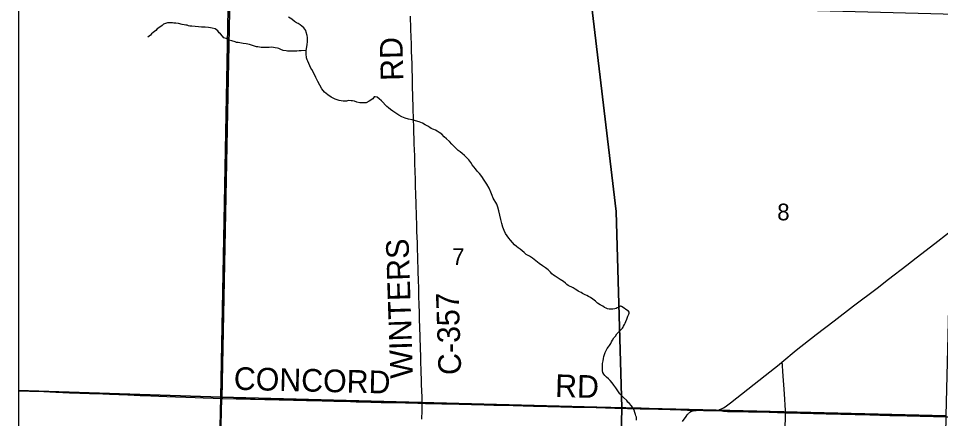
# Model space of a CAD drawing. Extents: x 0 to 34, y 0 to 22.
# Drawn here: x 23.9 to 25.055, y 17.356 to 17.857 of the extents above; entities that cross this region are included whole.
import ezdxf

# ---------------------------------------------------------------- set-up
doc = ezdxf.new("R2010")
doc.units = 0
for name, color, linetype in [('GM_X_County_Road', 7, 'Continuous'), ('GM_X_County_Road_Text', 7, 'Continuous'), ('GM_X_Minor_River', 7, 'Continuous'), ('GM_X_Section', 7, 'Continuous'), ('GM_X_Section_Text', 7, 'Continuous'), ('GM_X_State_Route', 7, 'Continuous'), ('GM_X_Township', 7, 'Continuous'), ('GM_X_Township_Road', 7, 'Continuous'), ('GM_X_Unincorporated', 7, 'Continuous'), ('SC_Scratch1', 7, 'Continuous'), ('SH_Border', 7, 'Continuous'), ('SH_Cut_Line', 7, 'Continuous')]:
    doc.layers.add(name, color=color, linetype=linetype)

msp = doc.modelspace()

# ---------------------------------------------------------------- linework, layer by layer
at = {"layer": 'GM_X_County_Road'}
for points in [[(24.4058, 17.3747), (24.4057, 17.3759), (24.4057, 17.3785), (24.4056, 17.3832), (24.4054, 17.3894), (24.4051, 17.399), (24.4048, 17.4059), (24.4046, 17.4119), (24.4044, 17.419), (24.4042, 17.4231), (24.4039, 17.4327), (24.4035, 17.4443), (24.4029, 17.4706), (24.4026, 17.4792), (24.4024, 17.4869), (24.402, 17.4996), (24.4017, 17.5074), (24.4014, 17.5178), (24.401, 17.5301), (24.4008, 17.5381), (24.4006, 17.5438), (24.4003, 17.5533), (24.4002, 17.559), (24.4, 17.5673), (24.3997, 17.5766), (24.3995, 17.5819), (24.3992, 17.5908), (24.3989, 17.5993), (24.3987, 17.6082), (24.3985, 17.6139), (24.3983, 17.6205), (24.3982, 17.6257), (24.3979, 17.6354), (24.3975, 17.648), (24.3973, 17.6546), (24.397, 17.6655), (24.3967, 17.6745), (24.3964, 17.6845), (24.3961, 17.6921), (24.3959, 17.6996), (24.3956, 17.7067), (24.3954, 17.713), (24.3951, 17.7226), (24.3949, 17.7285), (24.3948, 17.7337), (24.3946, 17.7412), (24.3944, 17.7484), (24.3942, 17.7555), (24.3937, 17.7754), (24.3935, 17.7832), (24.3933, 17.7927), (24.3931, 17.7995), (24.3928, 17.8082), (24.3925, 17.8153), (24.3924, 17.8213), (24.3923, 17.8245), (24.3922, 17.828), (24.3921, 17.8304), (24.392, 17.8331), (24.3916, 17.8439), (24.391, 17.8596)], [(23.9, 17.3905), (23.9139, 17.39), (23.9202, 17.3897), (23.9316, 17.3893), (23.9469, 17.3887), (23.9641, 17.388), (23.9767, 17.3875), (23.9888, 17.387), (24.0057, 17.3864), (24.014, 17.3861), (24.0369, 17.3852), (24.0524, 17.3846), (24.0658, 17.3841), (24.0859, 17.3833), (24.0968, 17.3829), (24.1097, 17.3824), (24.1215, 17.382), (24.1314, 17.3816), (24.1439, 17.3812), (24.155, 17.3809)], [(24.155, 17.3809), (24.156, 17.3809), (24.1733, 17.3805), (24.1853, 17.3802), (24.1965, 17.3799), (24.2104, 17.3796), (24.2241, 17.3793), (24.2409, 17.3789), (24.2607, 17.3784), (24.2769, 17.378), (24.2952, 17.3775), (24.3194, 17.3768), (24.3229, 17.3767), (24.3415, 17.3761), (24.3545, 17.3758), (24.3696, 17.3755), (24.3849, 17.3751), (24.4001, 17.3748), (24.4058, 17.3747), (24.4101, 17.3746), (24.4188, 17.3744), (24.4302, 17.3742), (24.452, 17.3737), (24.4677, 17.3733), (24.4709, 17.3732), (24.4834, 17.3728), (24.4956, 17.3725), (24.5067, 17.3722), (24.5451, 17.3712), (24.5632, 17.3708), (24.5795, 17.3704), (24.5946, 17.37), (24.6095, 17.3697), (24.6238, 17.3693), (24.6472, 17.3688), (24.6631, 17.3683), (24.679, 17.3679), (24.7017, 17.3673), (24.7163, 17.3669), (24.7296, 17.3666), (24.7315, 17.3665), (24.7363, 17.3664), (24.7382, 17.3663), (24.7395, 17.3661), (24.741, 17.3657), (24.7423, 17.3652), (24.7435, 17.3648)], [(24.7435, 17.3648), (24.7444, 17.3651), (24.7451, 17.3653), (24.7458, 17.3655), (24.7463, 17.3656), (24.7472, 17.3657), (24.7478, 17.3658), (24.7489, 17.3658), (24.7499, 17.3659), (24.752, 17.366), (24.7536, 17.3659), (24.7583, 17.3658), (24.7667, 17.3655), (24.7701, 17.3655), (24.7721, 17.3656), (24.7732, 17.3657), (24.7746, 17.3659), (24.7757, 17.3661), (24.7777, 17.3666), (24.7784, 17.3668)], [(24.7784, 17.3668), (24.78, 17.3659), (24.7807, 17.3656), (24.7811, 17.3654), (24.7818, 17.3653), (24.7825, 17.3651), (24.7833, 17.365), (24.785, 17.3648), (24.7864, 17.3647), (24.7884, 17.3646), (24.8403, 17.3634), (24.8607, 17.3629), (24.8636, 17.3628), (24.9117, 17.3615), (24.9664, 17.3601), (24.9915, 17.3595), (25.0133, 17.3591), (25.0789, 17.3574)]]:
    msp.add_lwpolyline(points, dxfattribs=at)
at = {"layer": 'GM_X_Minor_River'}
for points in [[(24.2606, 17.8167), (24.2543, 17.8164), (24.2517, 17.8161), (24.2486, 17.816), (24.2465, 17.8159), (24.2442, 17.8158), (24.2423, 17.8157), (24.2372, 17.816), (24.2355, 17.8163), (24.2315, 17.8168), (24.2287, 17.8179), (24.2263, 17.8193), (24.2246, 17.8197), (24.2214, 17.8202), (24.2197, 17.8205), (24.2176, 17.8207), (24.2142, 17.8205), (24.2113, 17.8204), (24.209, 17.8203), (24.2056, 17.8204), (24.2041, 17.8206), (24.1997, 17.8211), (24.198, 17.8214), (24.1958, 17.822), (24.193, 17.8229), (24.1896, 17.8242), (24.1851, 17.8251), (24.1813, 17.8256), (24.1752, 17.8266), (24.1733, 17.8268), (24.1716, 17.8273), (24.1673, 17.8287), (24.1637, 17.8296), (24.1602, 17.8315), (24.1574, 17.8325), (24.1555, 17.8345), (24.1532, 17.8374), (24.1513, 17.8388), (24.1499, 17.8411), (24.1482, 17.8425), (24.1464, 17.8439), (24.1428, 17.8448), (24.1407, 17.8451), (24.1382, 17.8455), (24.1341, 17.8459), (24.1293, 17.846), (24.1255, 17.8464), (24.1212, 17.8469), (24.117, 17.847), (24.1149, 17.8473), (24.113, 17.8476), (24.1113, 17.8482), (24.1098, 17.8484), (24.1077, 17.8489), (24.1049, 17.8494), (24.1006, 17.8503), (24.097, 17.8508), (24.0947, 17.8511), (24.0928, 17.8513), (24.0905, 17.8514), (24.0886, 17.8515), (24.0869, 17.8513), (24.0854, 17.8508), (24.0817, 17.8496), (24.0799, 17.848), (24.0759, 17.8451), (24.0737, 17.8438), (24.0721, 17.8418), (24.0686, 17.8394), (24.0668, 17.8374), (24.0653, 17.8359), (24.0637, 17.8347), (24.0619, 17.8334)], [(24.2662, 17.7947), (24.2626, 17.8034), (24.2617, 17.8051), (24.2609, 17.8076), (24.2605, 17.8126), (24.2606, 17.8167), (24.2616, 17.8239), (24.2622, 17.8279), (24.2622, 17.83), (24.2621, 17.833), (24.2618, 17.8353), (24.2603, 17.8395), (24.2602, 17.8416), (24.2576, 17.845), (24.255, 17.8471), (24.253, 17.8489), (24.2502, 17.8503), (24.2485, 17.8514), (24.2457, 17.853), (24.2424, 17.8559), (24.2381, 17.8582)], [(24.3634, 17.7449), (24.3613, 17.7467), (24.3548, 17.7535), (24.352, 17.7562), (24.3492, 17.758), (24.3468, 17.7588), (24.3457, 17.7586), (24.3439, 17.7562), (24.3393, 17.7531), (24.3356, 17.7513), (24.332, 17.751), (24.3276, 17.7513), (24.324, 17.7521), (24.321, 17.753), (24.3186, 17.7536), (24.3169, 17.7538), (24.3136, 17.7539), (24.3108, 17.7532), (24.3066, 17.753), (24.3019, 17.754), (24.2968, 17.7557), (24.2919, 17.7583), (24.2874, 17.7612), (24.2835, 17.7645), (24.2802, 17.7686), (24.2775, 17.7732), (24.2751, 17.778), (24.2726, 17.783), (24.2702, 17.7882), (24.2675, 17.793), (24.2662, 17.7947)], [(24.6289, 17.4981), (24.6255, 17.5003), (24.6227, 17.5026), (24.6196, 17.505), (24.6166, 17.5071), (24.6139, 17.5085), (24.6119, 17.5097), (24.61, 17.5105), (24.6066, 17.5121), (24.6049, 17.5133), (24.6029, 17.5143), (24.6012, 17.5153), (24.5993, 17.5165), (24.5973, 17.5177), (24.595, 17.5193), (24.5924, 17.5206), (24.5911, 17.5209), (24.5896, 17.5219), (24.5885, 17.5223), (24.587, 17.5236), (24.5853, 17.525), (24.5827, 17.5273), (24.5788, 17.5299), (24.575, 17.5323), (24.5724, 17.534), (24.5702, 17.5354), (24.5683, 17.537), (24.5663, 17.5391), (24.5637, 17.5417), (24.5603, 17.5442), (24.5566, 17.5468), (24.5525, 17.5497), (24.5482, 17.5532), (24.5439, 17.5564), (24.54, 17.5589), (24.5362, 17.5611), (24.5334, 17.5635), (24.5286, 17.5678), (24.5262, 17.5693), (24.524, 17.5713), (24.5215, 17.5734), (24.5189, 17.5762), (24.5165, 17.5789), (24.5145, 17.5816), (24.5121, 17.5843), (24.5101, 17.5872), (24.5085, 17.591), (24.5069, 17.5953), (24.5055, 17.5998), (24.5043, 17.605), (24.5031, 17.6105), (24.5017, 17.6159), (24.5005, 17.6205), (24.4992, 17.6243), (24.4948, 17.6316), (24.4936, 17.6351), (24.4918, 17.6393), (24.4895, 17.6441), (24.4869, 17.6493), (24.4836, 17.6543), (24.4805, 17.6587), (24.4774, 17.6626), (24.4746, 17.6657), (24.4726, 17.6686), (24.4706, 17.6709), (24.4685, 17.6736), (24.4665, 17.6765), (24.4641, 17.6796), (24.4613, 17.6825), (24.4586, 17.6853), (24.456, 17.6876), (24.4532, 17.6896), (24.4507, 17.6915), (24.4483, 17.6937), (24.4457, 17.6962), (24.443, 17.6995), (24.4398, 17.7026), (24.4363, 17.7059), (24.4331, 17.7087), (24.4302, 17.7118), (24.427, 17.7141), (24.4244, 17.7155), (24.4223, 17.7167), (24.4204, 17.7175), (24.4189, 17.7183), (24.4172, 17.7191), (24.4154, 17.7201), (24.4129, 17.7217), (24.4097, 17.7237), (24.406, 17.7257), (24.4019, 17.7275), (24.3975, 17.7287), (24.3934, 17.7299), (24.3888, 17.7306), (24.3845, 17.7319), (24.3804, 17.7335), (24.3764, 17.7357), (24.3727, 17.7382), (24.3691, 17.7406), (24.366, 17.7428), (24.3634, 17.7449)], [(24.6743, 17.3535), (24.6741, 17.3573), (24.6735, 17.3588), (24.6728, 17.3606), (24.6721, 17.3632), (24.6712, 17.3663), (24.6698, 17.369), (24.668, 17.3715), (24.665, 17.375), (24.6635, 17.3763), (24.662, 17.3781), (24.658, 17.382), (24.6535, 17.3867), (24.6517, 17.389), (24.65, 17.3915), (24.6482, 17.3942), (24.646, 17.3975), (24.6438, 17.4004), (24.6414, 17.4031), (24.639, 17.4054), (24.6365, 17.4074), (24.6345, 17.4095), (24.6332, 17.4114), (24.6321, 17.4132), (24.6316, 17.4155), (24.6317, 17.4179), (24.6318, 17.4212), (24.6318, 17.4244), (24.6323, 17.4278), (24.6327, 17.4308), (24.6334, 17.4335), (24.634, 17.4359), (24.635, 17.4385), (24.6362, 17.4408), (24.6376, 17.4432), (24.639, 17.4455), (24.6402, 17.4472), (24.6413, 17.4485), (24.6419, 17.4498), (24.6431, 17.4516), (24.6443, 17.4539), (24.6459, 17.4565), (24.6479, 17.4589), (24.6496, 17.4617), (24.6518, 17.464), (24.6537, 17.466), (24.6551, 17.4671), (24.6565, 17.4688), (24.6574, 17.4701), (24.658, 17.4712), (24.6594, 17.4736), (24.66, 17.475), (24.661, 17.477), (24.6621, 17.4802), (24.6635, 17.4838), (24.6645, 17.4864), (24.6649, 17.4877), (24.6651, 17.4889), (24.6642, 17.49), (24.6623, 17.4914), (24.6575, 17.4949), (24.6556, 17.4959), (24.6543, 17.4965), (24.6518, 17.4949), (24.6499, 17.4942), (24.6489, 17.4933), (24.647, 17.4929), (24.6445, 17.4926), (24.6418, 17.4925), (24.64, 17.4927), (24.6381, 17.4931), (24.6362, 17.4938), (24.6341, 17.4948), (24.6319, 17.4963), (24.6289, 17.4981)]]:
    msp.add_lwpolyline(points, dxfattribs=at)
at = {"layer": 'GM_X_Section'}
for points in [[(24.6177, 17.8744), (24.6487, 17.6151), (24.6558, 17.369), (24.1534, 17.3822), (24.1633, 17.8909)], [(25.0741, 17.8622), (25.0619, 17.3592), (24.6558, 17.369), (24.6487, 17.6151), (24.6177, 17.8744)], [(24.6558, 17.369), (24.6447, 16.8675), (24.1423, 16.8774), (24.1534, 17.3822)], [(24.6558, 17.369), (25.0619, 17.3592), (25.0529, 16.8591), (24.6447, 16.8675)]]:
    msp.add_lwpolyline(points, close=True, dxfattribs=at)
at = {"layer": 'GM_X_State_Route'}
for points in [[(24.7784, 17.3668), (24.7807, 17.3677), (24.7817, 17.3682), (24.7832, 17.3691), (24.7853, 17.3703), (24.7902, 17.3739), (24.7921, 17.3754), (24.8354, 17.4095), (24.8528, 17.4235), (24.8562, 17.4263), (24.8744, 17.4412), (24.8993, 17.4608), (24.9217, 17.4781), (24.9459, 17.4966), (24.9756, 17.5191), (24.9901, 17.5303), (25.0127, 17.5478), (25.0245, 17.5569), (25.0479, 17.575), (25.0651, 17.5883), (25.0869, 17.6052), (25.0993, 17.6147), (25.1102, 17.6228)], [(24.7319, 17.3521), (24.7363, 17.3582), (24.7378, 17.3602), (24.7388, 17.3614), (24.7395, 17.3622), (24.7399, 17.3625), (24.7403, 17.3629), (24.7407, 17.3633), (24.7413, 17.3636), (24.742, 17.3641), (24.7429, 17.3646), (24.7435, 17.3648)], [(24.7435, 17.3648), (24.7444, 17.3651), (24.7451, 17.3653), (24.7458, 17.3655), (24.7463, 17.3656), (24.7472, 17.3657), (24.7478, 17.3658), (24.7489, 17.3658), (24.7499, 17.3659), (24.752, 17.366), (24.7536, 17.3659), (24.7583, 17.3658), (24.7667, 17.3655), (24.7701, 17.3655), (24.7721, 17.3656), (24.7732, 17.3657), (24.7746, 17.3659), (24.7757, 17.3661), (24.7777, 17.3666), (24.7784, 17.3668)]]:
    msp.add_lwpolyline(points, dxfattribs=at)
at = {"layer": 'GM_X_Township'}
msp.add_lwpolyline([(24.1192, 16.1231), (24.1331, 16.5552), (24.135, 16.6155), (24.135, 16.6163), (24.1351, 16.6172), (24.135, 16.6181), (24.1432, 16.9162), (24.1548, 17.3809), (24.4058, 17.3748), (24.4708, 17.3735), (24.6801, 17.3692), (24.7295, 17.3668), (24.7393, 17.3664), (24.7413, 17.3663), (24.7492, 17.3661), (24.761, 17.3659), (24.7646, 17.3659), (24.7714, 17.3658), (24.7764, 17.3658), (24.8409, 17.3638), (24.8606, 17.3631), (25.5332, 17.3459)], dxfattribs=at)
at = {"layer": 'GM_X_Township_Road'}
for points in [[(24.8607, 17.3629), (24.8607, 17.3658), (24.8595, 17.3867), (24.8577, 17.4145), (24.8572, 17.4222), (24.8572, 17.423), (24.8571, 17.4236), (24.8569, 17.4243), (24.8568, 17.425), (24.8565, 17.4256), (24.8562, 17.4263)], [(24.4054, 17.3548), (24.4056, 17.3658), (24.4057, 17.3698), (24.4058, 17.3747)], [(24.8515, 16.9534), (24.8518, 16.9671), (24.8533, 17.0243), (24.8542, 17.0634), (24.8551, 17.1056), (24.8553, 17.112), (24.8554, 17.1171), (24.8562, 17.1538), (24.8569, 17.1969), (24.858, 17.2454), (24.8591, 17.292), (24.8597, 17.3199), (24.8604, 17.3423), (24.8607, 17.3595), (24.8607, 17.3629)]]:
    msp.add_lwpolyline(points, dxfattribs=at)
at = {"layer": 'GM_X_Unincorporated'}
for points in [[(23.9, 17.8996), (23.9, 17.3907), (24.1534, 17.3822), (24.1633, 17.8909)], [(23.9, 17.3907), (23.9, 16.8845), (24.1423, 16.8774), (24.1534, 17.3822)]]:
    msp.add_lwpolyline(points, close=True, dxfattribs=at)
at = {"layer": 'SC_Scratch1'}
for points in [[(23.9, 18.406), (23.9, 15.3715)], [(24.1192, 16.1231), (24.1331, 16.5552), (24.135, 16.6155), (24.135, 16.6163), (24.1351, 16.6172), (24.135, 16.6181), (24.1432, 16.9162), (24.1548, 17.3809), (24.1647, 17.8874)], [(24.1647, 17.8874), (24.1548, 17.3809), (24.4058, 17.3748), (24.6801, 17.3692), (24.7295, 17.3668), (24.7393, 17.3664), (24.7413, 17.3663), (24.7492, 17.3661), (24.761, 17.3659), (24.7646, 17.3659), (24.7714, 17.3658), (24.7764, 17.3658), (24.8409, 17.3638), (24.8606, 17.3631), (25.5332, 17.3459)]]:
    msp.add_lwpolyline(points, dxfattribs=at)
at = {"layer": 'SH_Border'}
msp.add_lwpolyline([(23.9, 20.2361), (23.9, 13.4361), (30.7, 13.4361), (30.7, 20.2361)], close=True, dxfattribs=at)
at = {"layer": 'SH_Cut_Line'}
msp.add_lwpolyline([(23.9, 20.2361), (23.9, 13.4361), (30.0382, 13.4361)], dxfattribs=at)

# ---------------------------------------------------------------- texts
at = {"layer": 'GM_X_County_Road_Text'}
for s, rotation, p in [('RD', 91.4816, (24.3823, 17.779)), ('WINTERS', 91.8579, (24.3943, 17.4063)), ('C-357', 91.9283, (24.4548, 17.4106)), ('CONCORD', 358.5928, (24.1695, 17.3917)), ('RD', 358.5193, (24.572, 17.3826))]:
    msp.add_text(s, height=0.02841, rotation=rotation, dxfattribs=at).set_placement(p)
at = {"layer": 'GM_X_Section_Text'}
for s, p in [('8', (24.8505, 17.6039)), ('7', (24.4432, 17.5479))]:
    msp.add_text(s, height=0.0209, rotation=0, dxfattribs=at).set_placement(p)

doc.saveas('drawing.dxf')
